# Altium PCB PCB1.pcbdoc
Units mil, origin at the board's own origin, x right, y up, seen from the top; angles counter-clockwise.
Board outline 4635.27 x 4240.16 mil, 2 copper layers (Top Layer, Bottom Layer); 8 components, 19 nets, 100 pads, 10 vias.
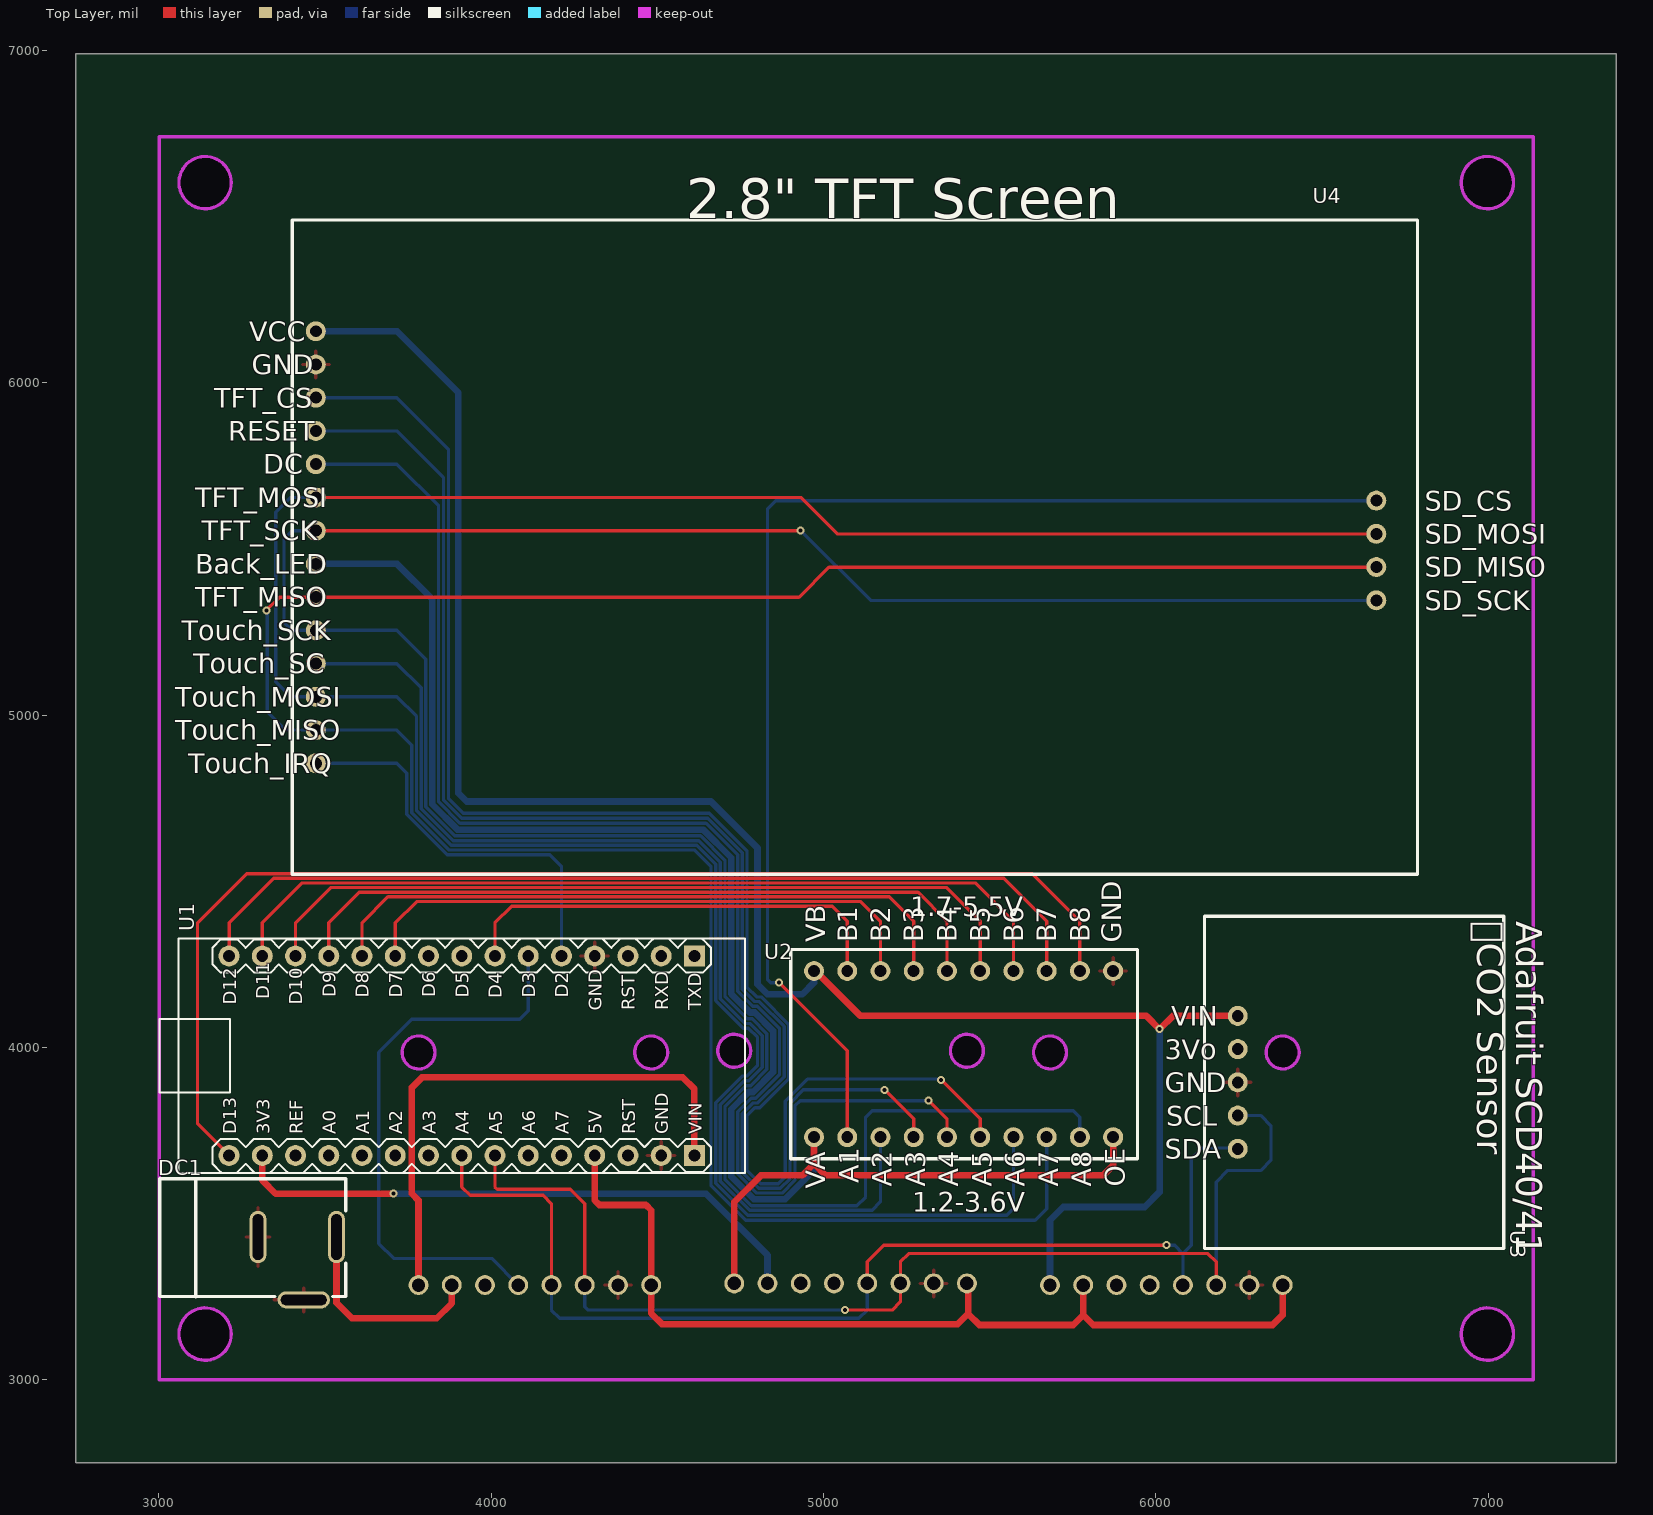
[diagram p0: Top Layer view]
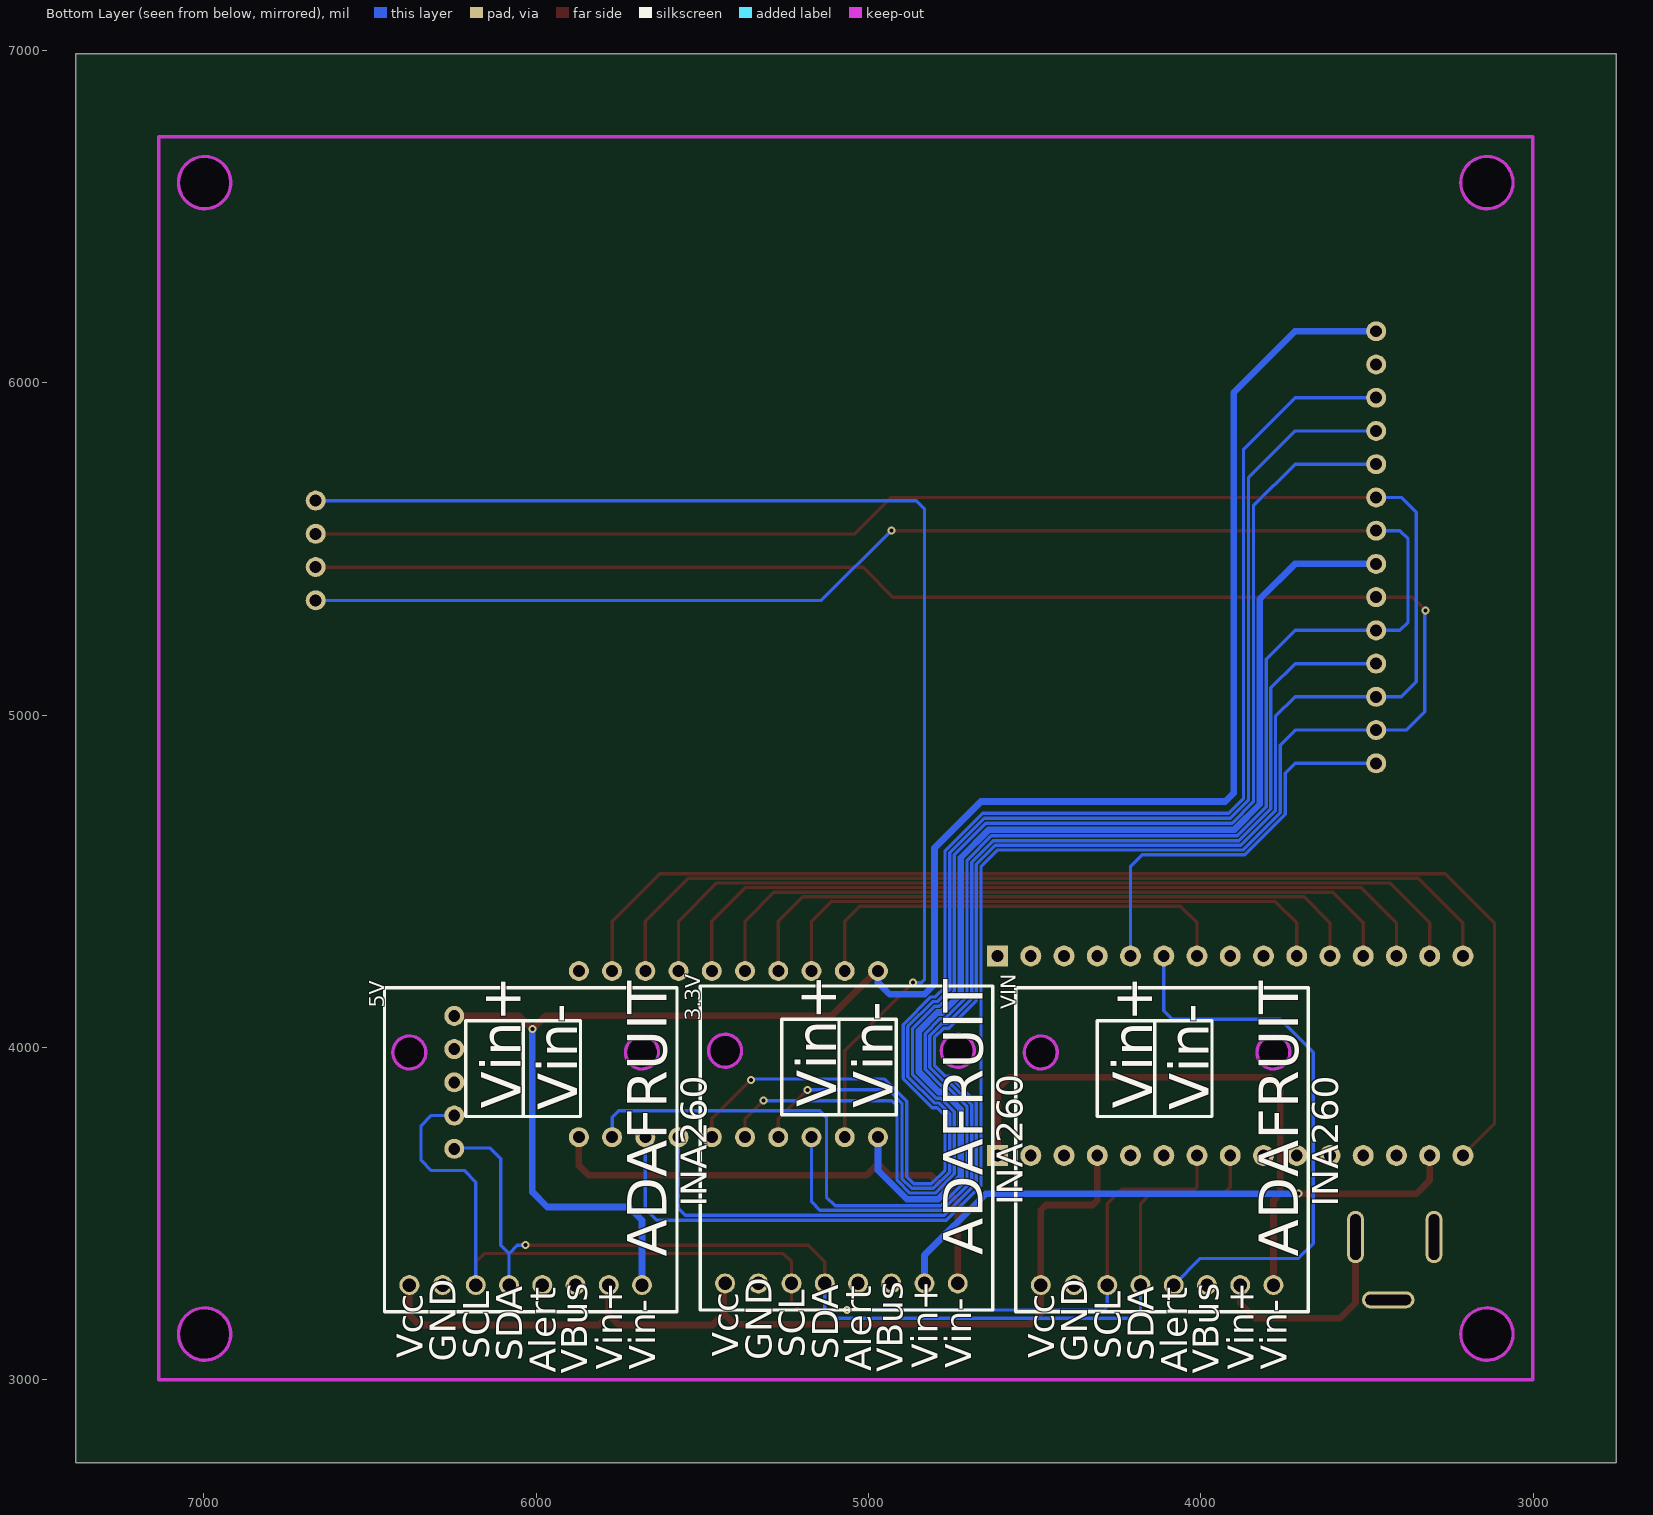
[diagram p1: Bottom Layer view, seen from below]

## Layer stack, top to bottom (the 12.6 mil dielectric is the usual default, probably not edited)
Top Layer: signal copper (thickness not stored)
Dielectric: dielectric 12.6, FR-4, Dk 4.8
Bottom Layer: signal copper (thickness not stored)

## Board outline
7385.27,2750 2750,2750 2750,6990.16 7385.27,6990.16
cut-out: 3217.95,6602.36 ccw(c3139.21,6602.36) 3060.47,6602.36 ccw(c3139.21,6602.36)
cut-out: 7076.22,6602.36 ccw(c6997.48,6601.94) 6918.74,6602.36 ccw(c6997.48,6602.78)
cut-out: 7076.22,3137.8 ccw(c6997.48,3137.38) 6918.74,3137.8 ccw(c6997.48,3138.21)
cut-out: 3217.95,3137.8 ccw(c3139.21,3137.8) 3060.47,3137.8 ccw(c3139.21,3137.8)

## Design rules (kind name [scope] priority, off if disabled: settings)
Clearance copperThickness1oz [All] p1: gap=7 ignorepadtopadclearanceinfootprint=FALSE except(4: Track-Track; 6: Track-SMDPad SMDPad-SMDPad Track-THPad SMDPad-THPad THPad-THPad Track-Via SMDPad-Via THPad-Via Via-Via Track-Fill SMDPad-Fill THPad-Fill Via-Fill Fill-Fill SMDPad-Region THPad-Region Via-Region Fill-Region Region-Region SMDPad-Poly THPad-Poly Via-Poly Fill-Poly Poly-Poly Track-Text SMDPad-Text THPad-Text Via-Text Fill-Text Region-Text Text-Text Track-Sheet SMDPad-Sheet THPad-Sheet Via-Sheet Fill-Sheet Region-Sheet Poly-Sheet Text-Sheet Track-Hole SMDPad-Hole THPad-Hole Via-Hole Fill-Hole Region-Hole Poly-Hole Text-Hole Sheet-Hole; 11.8: Track-Region Track-Poly Region-Poly Poly-Text)
Clearance copperThickness2oz [All] p1: gap=7 ignorepadtopadclearanceinfootprint=FALSE except(6: Track-SMDPad SMDPad-SMDPad Track-THPad SMDPad-THPad THPad-THPad Track-Via SMDPad-Via THPad-Via Via-Via Track-Fill SMDPad-Fill THPad-Fill Via-Fill Fill-Fill SMDPad-Region THPad-Region Via-Region Fill-Region Region-Region SMDPad-Poly THPad-Poly Via-Poly Fill-Poly Poly-Poly Track-Text SMDPad-Text THPad-Text Via-Text Fill-Text Region-Text Text-Text Track-Sheet SMDPad-Sheet THPad-Sheet Via-Sheet Fill-Sheet Region-Sheet Poly-Sheet Text-Sheet Track-Hole SMDPad-Hole THPad-Hole Via-Hole Fill-Hole Region-Hole Poly-Hole Text-Hole Sheet-Hole; 8: Track-Track; 11.8: Track-Region Track-Poly Region-Poly Poly-Text)
DiffPairsRouting differentialPair [All] p1: maxuncoupledlength=10 maxlimit=6 mostfreqgap=6 toplayer_minwidth=5 toplayer_prefwidth=10 toplayer_maxwidth=100 bottomlayer_minwidth=5 bottomlayer_prefwidth=10 bottomlayer_maxwidth=100
PasteMaskExpansion pasteMaskExpansion [All] p1:
PlaneConnect innerPlane [All] p1: planeconnectstyle=Relief reliefexpansion=20 reliefentries=4 reliefconductorwidth=10 reliefairgap=10
PolygonConnect copperRegion [All] p1: connectstyle=Relief reliefentries=4 reliefconductorwidth=10 polygonreliefangle="90 Angle" airgapwidth=10
RoutingVias viaSize [All] p1: viastyle="Through Hole" holewidth=12.0078 minholewidth=11.811 maxholewidth=248.0314 width=24.0158 minwidth=19.685 maxwidth=393.7008
SolderMaskExpansion solderMaskExpansion [All] p1: useseparateexpansions=TRUE expansion=2 expansionbottom=2
Width copperThickness1oz [All] p1: maxlimit=100 minlimit=5 preferedwidth=10
Width copperThickness2oz [All] p1: maxlimit=100 minlimit=8 preferedwidth=10

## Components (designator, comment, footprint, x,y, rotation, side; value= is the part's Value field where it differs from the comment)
3.3V "INA260 Breakout" "INA260 Breakout" 5431.41,3290.16 r90 bottom
5V "INA260 Breakout" "INA260 Breakout" 6381.41,3285.16 r90 bottom
DC1 "DC-005 2.0" DC-IN-TH_DC-5520-1 3416.41,3335.16 r0 top
U1 "ARDUINO_NANO" COMM-TH_ARDUINO_NANO 3911.41,3975.16 r0 top
U2 "8 Channel Level Shifter" "8 Channel Level Shifter Footprint" 4901.41,4295.16 r0 top
U3 "Adafruit SCD40/41 Breakout" "Adafruit SCD40/41" 6146.41,4395.16 r270 top
U4 "2.8\" TFT Screen (SPI, Touch, SD)" "2.8\" TFT Display Footprint 1" 3401.41,6490.16 r0 top
VIN "INA260 Breakout" "INA260 Breakout" 4481.41,3285.16 r90 bottom

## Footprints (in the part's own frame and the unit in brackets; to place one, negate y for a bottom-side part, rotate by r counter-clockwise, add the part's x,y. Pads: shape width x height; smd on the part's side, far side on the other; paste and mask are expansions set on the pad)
"2.8\" TFT Display Footprint 1" [mil]
  round 60 hole 36: 1(70.87,-335) 2(70.87,-435) 3(70.87,-535) 4(70.87,-635) 5(70.87,-735) 6(70.87,-835) 7(70.87,-935) 8(70.87,-1035) 9(70.87,-1135) 10(70.87,-1235) 11(70.87,-1335) 12(70.87,-1435) 13(70.87,-1535) 14(70.87,-1635) 15(3261.81,-844.49) 16(3261.81,-944.49) 17(3261.81,-1044.49) 18(3261.81,-1144.49)
  silkscreen extent 0,-1969 3386,0
"8 Channel Level Shifter Footprint" [mil]
  round 60 hole 36: 1(970,-64.96) 2(870,-64.96) 3(770,-64.96) 4(670,-64.96) 5(570,-64.96) 6(470,-64.96) 7(370,-64.96) 8(270,-64.96) 9(170,-64.96) 10(70,-64.96) 11(70,-564.96) 12(170,-564.96) 13(270,-564.96) 14(370,-564.96) 15(470,-564.96) 16(570,-564.96) 17(670,-564.96) 18(770,-564.96) 19(870,-564.96) 20(970,-564.96)
  silkscreen extent 0,-630 1043,0
"Adafruit SCD40/41" [mil]
  round 60 hole 36: 1(300,100) 2(400,100) 3(500,100) 4(600,100) 5(700,100)
  silkscreen extent 0,0 1000,900
COMM-TH_ARDUINO_NANO [mm]
  rect 1.6x1.6 hole 0.9: 1(17.78,7.62) 30(17.78,-7.62)
  round 1.6 hole 0.9: 2(15.24,7.62) 4(10.16,7.62) 6(5.08,7.62) 8(0,7.62) 10(-5.08,7.62) 12(-10.16,7.62) 14(-15.24,7.62) 15(-17.78,7.62) 16(-17.78,-7.62) 18(-12.7,-7.62) 20(-7.62,-7.62) 22(-2.54,-7.62) 24(2.54,-7.62) 26(7.62,-7.62) 28(12.7,-7.62) 29(15.24,-7.62)
  round 1.6 hole 0.9 copper offset 0,0: 3(12.7,7.62)
  round 1.6 hole 0.9 copper offset 0.001,0: 5(7.619,7.62) 7(2.539,7.62) 9(-2.541,7.62) 11(-7.621,7.62) 13(-12.701,7.62)
  round 1.6 hole 0.9 copper offset -0.001,0: 17(-15.239,-7.62) 19(-10.159,-7.62) 21(-5.079,-7.62) 23(0.001,-7.62) 25(5.081,-7.62) 27(10.161,-7.62)
  silkscreen extent -23.11,-8.97 21.67,8.97
DC-IN-TH_DC-5520-1 [mm]
  oval 4x1.3 hole 0.8 slot 3.5 at 0 deg: 2(0.5,-2.4)
  oval 1.3x4 hole 0.8 slot 3.5 at 90 deg: 3(-3,2.4) 4(3,2.4)
  silkscreen extent -10.5,-2.16 3.7,6.85
"INA260 Breakout" [mil]
  round 60 hole 40.16: 1(0,0) 2(0,-100) 3(0,-200) 4(0,-300) 5(0,-400) 6(0,-500) 7(0,-600) 8(0,-700)
  Multi-Layer board cut-out: 700,49.61 724.7,42.88 742.75,24.73 749.35,0 742.75,-24.73 724.7,-42.87 700,-49.61 700,-49.6 675.31,-42.88 657.25,-24.73 650.65,0 657.25,24.73 675.3,42.88 700,49.61
  Multi-Layer board cut-out: 700,-650.39 724.7,-657.12 742.75,-675.27 749.35,-700 742.75,-724.73 724.7,-742.87 700,-749.61 700,-749.6 675.31,-742.88 657.25,-724.73 650.65,-700 657.25,-675.27 675.3,-657.12 700,-650.39
  Multi-Layer keep-out circle w10: c700,0 r49.61
  Multi-Layer keep-out circle w10: c700,-700 r49.61
  silkscreen extent -80,-805 895,75

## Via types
v1: diameter 24.02, hole 12.01, Top Layer to Bottom Layer, 10 vias

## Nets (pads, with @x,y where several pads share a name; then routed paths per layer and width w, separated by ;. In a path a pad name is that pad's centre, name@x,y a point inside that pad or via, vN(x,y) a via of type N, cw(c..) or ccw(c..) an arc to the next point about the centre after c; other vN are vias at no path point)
+3V: 3.3V.7 U1.17 | length 1773.2
  Top Layer w20: U1.17 3311.41,3600.16 3351.41,3560.16 v1(3706.41,3560.16)
  Bottom Layer w20: v1(3706.41,3560.16) 4646.41,3560.16 4831.41,3375.16 3.3V.7
+3VS: 3.3V.8 U2.11 U2.20 U4.8 | length 5095.9
  Top Layer w20: 3.3V.8 4731.41,3535.16 4811.41,3615.16 4936.41,3615.16 4971.41,3650.16 ; U2.11 4971.41,3650.16 ; U2.20 5871.41,3645.16 5841.41,3615.16 5006.41,3615.16 4971.41,3650.16
  Bottom Layer w20: U4.8 3716.41,5455.16 3822.48,5349.09 3822.48,4731.88 3898.65,4655.71 4637.76,4655.71 4722.48,4570.99 4722.48,4161.49 4778.81,4105.16 4792.95,4105.16 4848.46,4049.65 4848.46,3926.17 4788.43,3866.14 4774.29,3866.14 4722.48,3814.33 4722.48,3611.7 4790.99,3543.19 4883.91,3543.19 4971.41,3630.69 U2.11
+5V: 3.3V.1 5V.1 5V.7 U1.27 VIN.1 | length 2877.9
  Top Layer w20: U1.27 4311.41,3540.16 4325.56,3526.02 4465.56,3526.02 4481.41,3510.16 VIN.1 4481.41,3200.16 4513.91,3167.66 5403.91,3167.66 5435.16,3198.91 ; 3.3V.1 5435.16,3286.41 5435.16,3198.91 ; 5V.7 5781.41,3195.16 ; 5V.1 6381.41,3195.16 6351.41,3165.16 5811.41,3165.16 5781.41,3195.16 ; 5435.16,3198.91 5468.91,3165.16 5751.41,3165.16 5781.41,3195.16
+5VS: 5V.8 U2.10 U3.1 U4.1 | length 5735.4
  Top Layer w20: U2.10 4976.38,4230.2 5111.41,4095.16 5971.41,4095.16 v1(6011.41,4055.16) 6051.41,4095.16 U3.1
  Bottom Layer w20: U4.1 3716.41,6155.16 3901.41,5970.16 3901.41,4765.16 3926.41,4740.16 4661.41,4740.16 4801.41,4600.16 4801.41,4190.16 4831.41,4160.16 4936.48,4160.16 4971.41,4195.09 U2.10 ; 5V.8 5681.41,3480.16 5721.41,3520.16 5966.41,3520.16 6011.41,3565.16 v1(6011.41,4055.16)
ALERT: U1.6 VIN.5 | length 1713.6
  Bottom Layer w10: VIN.5 4001.41,3365.16 3706.41,3365.16 3661.41,3410.16 3661.41,3985.16 3761.41,4085.16 4086.41,4085.16 4111.41,4110.16 U1.6
DC: 
GND: 3.3V.2 5V.2 DC1.2 DC1.3 U1.4 U1.29 U2.1 U3.3 U4.2 VIN.2
IRQ: U1.5 U4.14 | length 1209.8
  Bottom Layer w10: U4.14 3716.41,4855.16 3746.41,4825.16 3746.41,4701.77 3868.02,4580.16 4176.41,4580.16 4211.41,4545.16 U1.5
MISO: U1.15 U2.3 U2.18 U4.9 U4.13 U4.17 | length 10409
  Top Layer w10: U1.15 3211.41,4375.16 3345.51,4509.25 5542.32,4509.25 5671.41,4380.16 U2.3 ; v1(3323.42,5315.16) 3363.42,5355.16 U4.9 4926.41,5355.16 5016.41,5445.16 6662.71,5445.16 U4.17
  Bottom Layer w10: v1(3323.42,5315.16) 3326.41,5312.17 3326.41,5010.16 3381.41,4955.16 U4.13 3716.41,4955.16 3761.41,4910.16 3761.41,4706.59 3873.83,4594.17 4612.4,4594.17 4661.41,4545.16 4661.41,3585.16 4766.41,3480.16 5636.41,3480.16 5671.41,3515.16 U2.18
MOSI: U1.14 U2.4 U2.17 U4.6 U4.12 U4.16 | length 10450.7
  Top Layer w10: U1.14 3311.41,4375.16 3431.49,4495.24 5456.34,4495.24 5571.41,4380.16 U2.4 ; U4.6 4931.41,5655.16 5041.41,5545.16 6662.71,5545.16 U4.16
  Bottom Layer w10: U4.12@3471.41,5055.16 3396.41,5055.16 3351.41,5100.16 3351.41,5610.16 3396.41,5655.16 U4.6 ; U4.12 3716.41,5055.16 3775.43,4996.14 3775.43,4712.39 3879.64,4608.19 4618.2,4608.19 4675.43,4550.96 4675.43,4141.32 4758.64,4058.11 4773.46,4058.11 4801.41,4030.16 4801.41,3946.02 4769.57,3914.17 4755.43,3914.17 4675.43,3834.17 4675.43,3591.14 4771.41,3495.16 5551.41,3495.16 5571.41,3515.16 U2.17
RESET: U1.11 U2.7 U2.14 U4.4 | length 6314.9
  Top Layer w10: U1.11 3611.41,4375.16 3689.45,4453.19 5198.38,4453.19 5271.41,4380.16 U2.7 ; v1(5183.91,3872.66) 5271.41,3785.16 U2.14
  Bottom Layer w10: U4.4 3716.41,5855.16 3856.41,5715.16 3856.41,4745.16 3911.41,4690.16 4651.41,4690.16 4755.51,4586.06 4755.51,4175.17 4792.49,4138.19 4806.67,4138.19 4881.49,4063.37 4881.49,3912.49 4802.12,3833.11 4787.97,3833.11 4755.51,3800.65 4755.51,3625.38 4804.67,3576.22 4870.23,3576.22 4899.21,3605.2 4899.21,3832.77 4939.09,3872.66 v1(5183.91,3872.66)
SCK: U1.16 U2.2 U2.19 U4.7 U4.10 U4.18 | length 11691.9
  Top Layer w10: U1.16 3116.41,3770.16 3116.41,4375.16 3264.52,4523.27 5628.31,4523.27 5771.41,4380.16 U2.2 ; U4.7 v1(4931.41,5555.16)
  Bottom Layer w10: U4.7 3401.41,5555.16 3376.41,5530.16 3376.41,5280.16 3401.41,5255.16 U4.10 3716.41,5255.16 3803.46,5168.11 3803.46,4724 3890.77,4636.69 4629.88,4636.69 ; 4629.94,4636.63 4703.46,4563.11 4703.46,4153.61 4770.93,4086.14 4785.07,4086.14 4829.45,4041.77 4829.45,3934.05 4780.56,3885.16 4766.41,3885.16 4703.46,3822.2 4703.46,3603.83 4783.11,3524.17 5100.43,3524.17 5126.41,3550.16 5126.41,3790.16 5146.41,3810.16 5751.41,3810.16 5771.41,3790.16 U2.19 ; v1(4931.41,5555.16) 5141.41,5345.16 6662.71,5345.16 U4.18
SCL: 3.3V.3 5V.3 U1.24 U3.4 VIN.3 | length 3540.3
  Top Layer w10: U1.24 4011.41,3580.16 4018.49,3573.09 4238.49,3573.09 4281.41,3530.16 VIN.3 ; v1(5064.45,3210.16) 5206.41,3210.16 5231.41,3235.16 3.3V.3 5231.41,3355.16 5256.41,3380.16 6156.41,3380.16 6181.41,3355.16 5V.3
  Bottom Layer w10: VIN.3 4281.41,3220.16 4291.41,3210.16 v1(5064.45,3210.16) ; 5V.3 6181.41,3595.16 6216.41,3630.16 6316.41,3630.16 6346.41,3660.16 6346.41,3765.16 6316.41,3795.16 U3.4
SD_CS: U1.7 U2.9 U2.12 U4.15 | length 5195.7
  Top Layer w10: U1.7 4011.41,4375.16 4061.41,4425.16 5026.41,4425.16 5071.41,4380.16 U2.9 ; v1(4866.41,4195.16) 5071.41,3990.16 U2.12
  Bottom Layer w10: v1(4866.41,4195.16) 4841.41,4195.16 4831.41,4205.16 4831.41,5620.16 4856.41,5645.16 6662.71,5645.16 U4.15
SDA: 3.3V.4 5V.4 U1.23 U3.5 VIN.4 | length 3347.3
  Top Layer w10: U1.23 3911.41,3580.16 3936.41,3555.16 4156.41,3555.16 4181.41,3530.16 VIN.4 ; 3.3V.4 5131.41,3355.16 5181.41,3405.16 v1(6031.41,3405.16)
  Bottom Layer w10: VIN.4 4181.41,3210.16 4206.41,3185.16 5106.41,3185.16 5131.41,3210.16 3.3V.4 ; v1(6031.41,3405.16) 6056.41,3405.16 6081.41,3380.16 ; 5V.4 6081.41,3380.16 ; U3.5 6243.91,3697.66 6138.91,3697.66 6106.41,3665.16 6106.41,3405.16 6081.41,3380.16
T_CS: U1.10 U2.8 U2.13 U4.11 | length 5243.2
  Top Layer w10: U1.10 3711.41,4375.16 3775.43,4439.17 5112.4,4439.17 5171.41,4380.16 U2.8
  Bottom Layer w10: U4.11 3716.41,5155.16 3789.45,5082.13 3789.45,4718.2 3885.24,4622.4 4624.17,4622.4 4689.45,4557.13 4689.45,4147.13 4764.45,4072.13 4779.27,4072.13 4815.43,4035.96 4815.43,3939.85 4775.74,3900.16 4761.59,3900.16 4689.45,3828.01 4689.45,3598.02 4777.31,3510.16 5146.41,3510.16 5171.41,3535.16 U2.13
TFT_CS: U1.13 U2.5 U2.16 U4.3 | length 7041.3
  Top Layer w10: U1.13 3411.41,4375.16 3517.48,4481.22 5370.35,4481.22 5471.41,4380.16 U2.5 ; v1(5353.91,3902.66) 5471.41,3785.16 U2.16
  Bottom Layer w10: U4.3 3716.41,5955.16 3871.41,5800.16 3871.41,4749.98 3916.24,4705.16 4656.41,4705.16 4769.52,4592.05 4769.52,4182.05 4799.37,4152.2 4812.48,4152.2 4895.51,4069.17 4895.51,3906.68 4807.92,3819.09 4793.78,3819.09 4769.52,3794.84 4769.52,3631.19 4810.48,3590.24 4864.42,3590.24 4885.2,3611.01 4885.2,3838.58 4951.77,3905.16 5351.41,3905.16 v1(5353.91,3902.66)
VIN: DC1.4 VIN.7 | length 637.6
  Top Layer w20: DC1.4 3534.53,3232.05 3581.41,3185.16 3836.41,3185.16 3881.41,3230.16 VIN.7
VINS: U1.30 VIN.8 | length 1680.2
  Top Layer w20: VIN.8 3781.41,3540.16 3761.41,3560.16 3761.41,3880.16 3791.41,3910.16 4576.41,3910.16 4611.41,3875.16 U1.30
pads on no net: 3.3V.5 3.3V.6 5V.5 5V.6 U1.1 U1.2 U1.3 U1.8 U1.9 U1.12 U1.18 U1.19 U1.20 U1.21 U1.22 U1.25 U1.26 U1.28 U2.6 U2.15 U3.2 U4.5 VIN.6
copper on no net: | length 6521.3
  Top Layer w10: 3511.41,4275.16 3511.41,4375.16 3603.46,4467.2 5284.37,4467.2 5371.41,4380.16 5371.41,4230.2 ; v1(5316.41,3840.16) 5371.41,3785.16 5371.41,3730.2
  Bottom Layer w10: 3472.28,5755.16 3716.41,5755.16 3841.49,5630.08 3841.49,4739.76 3906.09,4675.16 4646.59,4675.16 4741.49,4580.26 4741.49,4169.36 4786.68,4124.17 4800.83,4124.17 4867.48,4057.52 4867.48,3918.29 4796.31,3847.13 4782.17,3847.13 4741.49,3806.45 4741.49,3619.58 4798.87,3562.2 4876.03,3562.2 4914.13,3600.3 4914.13,3824.84 4929.45,3840.16 v1(5316.41,3840.16)

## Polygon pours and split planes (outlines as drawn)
GND on Top Layer (solid, remove dead copper): 3001.41,3000 7135.27,3000 7135.27,6740.16 3001.41,6740.16

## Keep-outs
Board Outline Layer:
  lines w10: 3001.41,3000 7135.27,3000 7135.27,6740.16 3001.41,6740.16 3001.41,3000
Multi-Layer:
  circle w10: c3139.21,6602.36 r78.74
  circle w10: c6997.48,6602.36 r78.74
  circle w10: c6997.48,3137.8 r78.74
  circle w10: c3139.21,3137.8 r78.74

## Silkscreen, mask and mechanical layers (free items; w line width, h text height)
Mechanical Layer:
  circle w1: c3139.21,6602.36 r78.74
  circle w1: c6997.48,6602.36 r78.74
  circle w1: c6997.48,3137.8 r78.74
  circle w1: c3139.21,3137.8 r78.74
